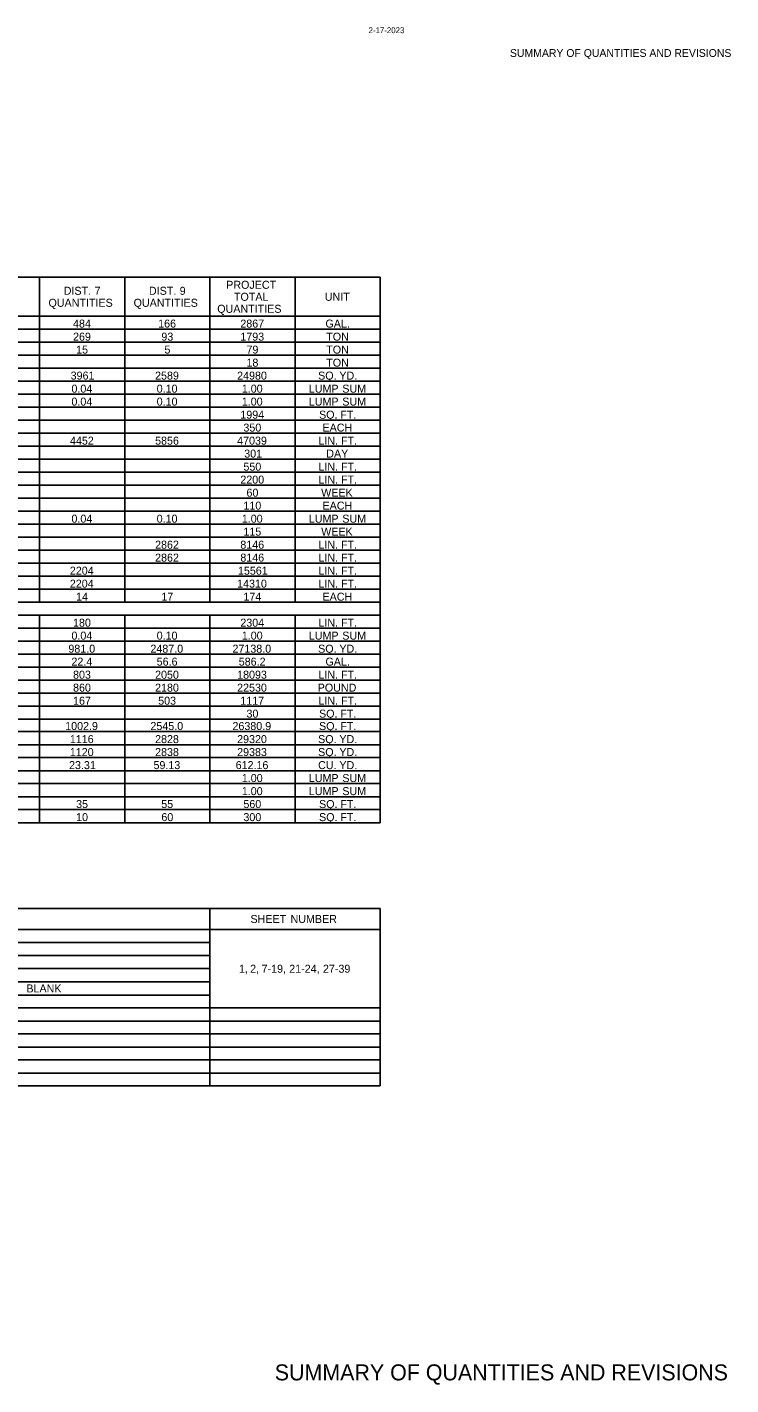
# Model space of a CAD drawing. Extents: x 544255 to 1930787, y -1947044 to 596640.
# Drawn here: x 556640 to 557167, y -1947044 to -1946026 of the extents above; entities that cross this region are included whole.
import ezdxf

# ---------------------------------------------------------------- set-up
doc = ezdxf.new("R2010")
doc.units = 0
for name, color, linetype in [('Default', 7, 'Continuous'), ('R_Border', 7, 'Continuous'), ('R_Border Prem', 7, 'Continuous')]:
    doc.layers.add(name, color=color, linetype=linetype)

msp = doc.modelspace()

# ---------------------------------------------------------------- linework, layer by layer
at = {"layer": 'Default'}
for p, q in [((555898, -1946213.6), (556904.2, -1946213.6)), ((556457.1, -1946213.6), (556904.2, -1946213.6)), ((556648.7, -1946457.4), (556648.7, -1946213.6)), ((556648.7, -1946242.9), (556648.7, -1946213.6)), ((556712.6, -1946457.4), (556712.6, -1946213.6)), ((556712.6, -1946242.9), (556712.6, -1946213.6)), ((556776.5, -1946457.4), (556776.5, -1946213.6)), ((556840.3, -1946457.4), (556840.3, -1946213.6)), ((556840.3, -1946457.4), (556840.3, -1946213.6)), ((556904.2, -1946622.7), (556904.2, -1946213.6)), ((555898, -1946242.9), (556904.2, -1946242.9)), ((555898, -1946242.9), (556904.2, -1946242.9)), ((555898, -1946252.6), (556904.2, -1946252.6)), ((555898, -1946262.4), (556904.2, -1946262.4)), ((555898, -1946272.1), (556904.2, -1946272.1)), ((555898, -1946281.9), (556904.2, -1946281.9)), ((555898, -1946291.6), (556904.2, -1946291.6)), ((555898, -1946301.4), (556904.2, -1946301.4)), ((555898, -1946311.1), (556904.2, -1946311.1)), ((555898, -1946320.9), (556904.2, -1946320.9)), ((555898, -1946330.6), (556904.2, -1946330.6)), ((555898, -1946340.4), (556904.2, -1946340.4)), ((555898, -1946350.1), (556904.2, -1946350.1)), ((555898, -1946359.9), (556904.2, -1946359.9)), ((555898, -1946369.6), (556904.2, -1946369.6)), ((555898, -1946379.4), (556904.2, -1946379.4)), ((555898, -1946389.1), (556904.2, -1946389.1)), ((555898, -1946398.9), (556904.2, -1946398.9)), ((555898, -1946408.6), (556904.2, -1946408.6)), ((555898, -1946418.4), (556904.2, -1946418.4)), ((555898, -1946428.1), (556904.2, -1946428.1)), ((555898, -1946437.9), (556904.2, -1946437.9)), ((555898, -1946447.6), (556904.2, -1946447.6)), ((555898, -1946457.4), (556904.2, -1946457.4)), ((555898, -1946457.4), (556904.2, -1946457.4)), ((555898, -1946467.1), (556904.2, -1946467.1)), ((555898, -1946467.1), (556904.2, -1946467.1)), ((556648.7, -1946622.7), (556648.7, -1946467.1)), ((556712.6, -1946622.7), (556712.6, -1946467.1)), ((556776.5, -1946622.7), (556776.5, -1946467.1)), ((556840.3, -1946622.7), (556840.3, -1946467.1)), ((555898, -1946476.9), (556904.2, -1946476.9)), ((555898, -1946486.6), (556904.2, -1946486.6)), ((555898, -1946496.4), (556904.2, -1946496.4)), ((555898, -1946506.1), (556904.2, -1946506.1)), ((555898, -1946515.9), (556904.2, -1946515.9)), ((555898, -1946525.6), (556904.2, -1946525.6)), ((555898, -1946535.4), (556904.2, -1946535.4)), ((555898, -1946545.1), (556904.2, -1946545.1)), ((555898, -1946554.4), (556904.2, -1946554.4)), ((555898, -1946564.2), (556904.2, -1946564.2)), ((555898, -1946573.9), (556904.2, -1946573.9)), ((555898, -1946583.7), (556904.2, -1946583.7)), ((555898, -1946593.4), (556904.2, -1946593.4)), ((555898, -1946603.2), (556904.2, -1946603.2)), ((555898, -1946612.9), (556904.2, -1946612.9)), ((555898, -1946622.7), (556904.2, -1946622.7)), ((555898, -1946687.1), (556904.2, -1946687.1)), ((556776.5, -1946702.7), (556776.5, -1946687.1)), ((556776.5, -1946820.1), (556776.5, -1946687.1)), ((556904.2, -1946820.1), (556904.2, -1946687.1)), ((555898, -1946702.7), (556904.2, -1946702.7)), ((555968.7, -1946712.4), (556776.5, -1946712.4)), ((555968.7, -1946722.2), (556776.5, -1946722.2)), ((555968.7, -1946731.9), (556776.5, -1946731.9)), ((555968.7, -1946742.1), (556776.5, -1946742.1)), ((555968.7, -1946751.9), (556776.5, -1946751.9)), ((555898, -1946761.6), (556904.2, -1946761.6)), ((556776.5, -1946761.6), (556904.2, -1946761.6)), ((555898, -1946771.4), (556904.2, -1946771.4)), ((555898, -1946781.1), (556904.2, -1946781.1)), ((555898, -1946790.9), (556904.2, -1946790.9)), ((555898, -1946800.6), (556904.2, -1946800.6)), ((555898, -1946810.4), (556904.2, -1946810.4)), ((555898, -1946820.1), (556904.2, -1946820.1))]:
    msp.add_line(p, q, dxfattribs=at)

# ---------------------------------------------------------------- texts
for s, p in [('PROJECT', (556788.7, -1946222.3)), ('DIST.', (556666.9, -1946226.8)), (' 7', (556687.8, -1946226.8)), ('DIST.', (556730.8, -1946226.8)), (' 9', (556751.6, -1946226.8)), ('TOTAL', (556794.5, -1946231.3)), ('UNIT', (556862.6, -1946231.3)), ('QUANTITIES', (556655.5, -1946235.8)), ('QUANTITIES', (556719.3, -1946235.8)), ('QUANTITIES', (556782, -1946240.3)), ('484', (556673.9, -1946251.4)), ('166', (556737.7, -1946251.4)), ('2867', (556799.3, -1946251.4)), ('GAL.', (556863.1, -1946251.4)), ('269', (556673.9, -1946261.2)), ('93', (556740.1, -1946261.2)), ('1793', (556799.3, -1946261.2)), ('TON', (556863.7, -1946261.2)), ('15', (556676.2, -1946270.9)), ('5', (556742.4, -1946270.9)), ('79', (556803.9, -1946270.9)), ('TON', (556863.7, -1946270.9)), ('18', (556803.9, -1946280.7)), ('TON', (556863.7, -1946280.7)), ('3961', (556672.1, -1946290.4)), ('2589', (556735.4, -1946290.4)), ('24980', (556796.9, -1946290.4)), ('SQ.', (556857.6, -1946290.4)), (' YD.', (556871.3, -1946290.4)), ('0.04', (556672.7, -1946300.2)), ('0.10', (556736.6, -1946300.2)), ('1.00', (556800.4, -1946300.2)), ('LUMP', (556850.6, -1946300.2)), (' SUM', (556873.5, -1946300.2)), ('0.04', (556672.7, -1946309.9)), ('0.10', (556736.6, -1946309.9)), ('1.00', (556800.4, -1946309.9)), ('LUMP', (556850.6, -1946309.9)), (' SUM', (556873.5, -1946309.9)), ('1994', (556799.3, -1946319.7)), ('SQ.', (556858.3, -1946319.7)), (' FT.', (556872, -1946319.7)), ('350', (556801.6, -1946329.4)), ('EACH', (556860.9, -1946329.4)), ('4452', (556671.6, -1946339.2)), ('5856', (556735.4, -1946339.2)), ('47039', (556796.9, -1946339.2)), ('LIN.', (556857.8, -1946339.2)), (' FT.', (556872.5, -1946339.2)), ('301', (556802.2, -1946348.9)), ('DAY', (556863.7, -1946348.9)), ('550', (556801.6, -1946358.7)), ('LIN.', (556857.8, -1946358.7)), (' FT.', (556872.5, -1946358.7)), ('2200', (556799.3, -1946368.4)), ('LIN.', (556857.8, -1946368.4)), (' FT.', (556872.5, -1946368.4)), ('60', (556803.9, -1946378.2)), ('WEEK', (556859.9, -1946378.2)), ('110', (556801.6, -1946387.9)), ('EACH', (556860.9, -1946387.9)), ('0.04', (556672.7, -1946397.7)), ('0.10', (556736.6, -1946397.7)), ('1.00', (556800.4, -1946397.7)), ('LUMP', (556850.6, -1946397.7)), (' SUM', (556873.5, -1946397.7)), ('115', (556801.6, -1946407.4)), ('WEEK', (556859.9, -1946407.4)), ('2862', (556735.4, -1946417.2)), ('8146', (556799.3, -1946417.2)), ('LIN.', (556857.8, -1946417.2)), (' FT.', (556872.5, -1946417.2)), ('2862', (556735.4, -1946426.9)), ('8146', (556799.3, -1946426.9)), ('LIN.', (556857.8, -1946426.9)), (' FT.', (556872.5, -1946426.9)), ('2204', (556671.5, -1946436.7)), ('2204', (556671.5, -1946446.4)), ('14310', (556796.9, -1946446.4)), ('15561', (556797.5, -1946436.7)), ('LIN.', (556857.8, -1946436.7)), ('LIN.', (556857.8, -1946446.4)), (' FT.', (556872.5, -1946436.7)), (' FT.', (556872.5, -1946446.4)), ('14', (556676.2, -1946456.2)), ('17', (556740.1, -1946456.2)), ('174', (556801.6, -1946456.2)), ('EACH', (556860.9, -1946456.2)), ('180', (556673.9, -1946475.7)), ('2304', (556799.3, -1946475.7)), ('LIN.', (556857.8, -1946475.7)), (' FT.', (556872.5, -1946475.7)), ('0.04', (556672.7, -1946485.4)), ('0.10', (556736.6, -1946485.4)), ('1.00', (556800.4, -1946485.4)), ('LUMP', (556850.6, -1946485.4)), (' SUM', (556873.5, -1946485.4)), ('981.0', (556670.4, -1946495.2)), ('2487.0', (556731.9, -1946495.2)), ('27138.0', (556793.4, -1946495.2)), ('SQ.', (556857.6, -1946495.2)), (' YD.', (556871.3, -1946495.2)), ('22.4', (556672.7, -1946504.9)), ('56.6', (556736.6, -1946504.9)), ('586.2', (556798.1, -1946504.9)), ('GAL.', (556863.1, -1946504.9)), ('803', (556673.9, -1946514.7)), ('2050', (556735.4, -1946514.7)), ('18093', (556796.9, -1946514.7)), ('LIN.', (556857.8, -1946514.7)), (' FT.', (556872.5, -1946514.7)), ('860', (556673.9, -1946524.4)), ('2180', (556735.4, -1946524.4)), ('22530', (556796.9, -1946524.4)), ('POUND', (556857.3, -1946524.4)), ('167', (556673.9, -1946534.2)), ('503', (556737.7, -1946534.2)), ('1117', (556799.3, -1946534.2)), ('LIN.', (556857.8, -1946534.2)), (' FT.', (556872.5, -1946534.2)), ('30', (556803.9, -1946543.9)), ('SQ.', (556858.3, -1946543.9)), (' FT.', (556872, -1946543.9)), ('1002.9', (556668, -1946553.2)), ('2545.0', (556731.9, -1946553.2)), ('26380.9', (556793.4, -1946553.2)), ('SQ.', (556858.3, -1946553.2)), (' FT.', (556872, -1946553.2)), ('1116', (556671.5, -1946563)), ('2828', (556735.4, -1946563)), ('29320', (556796.9, -1946563)), ('SQ.', (556857.6, -1946563)), (' YD.', (556871.3, -1946563)), ('1120', (556671.5, -1946572.7)), ('2838', (556735.4, -1946572.7)), ('29383', (556796.9, -1946572.7)), ('SQ.', (556857.6, -1946572.7)), (' YD.', (556871.3, -1946572.7)), ('23.31', (556670.9, -1946582.5)), ('59.13', (556734.2, -1946582.5)), ('612.16', (556795.8, -1946582.5)), ('CU.', (556857.6, -1946582.5)), (' YD.', (556871.3, -1946582.5)), ('1.00', (556800.4, -1946592.2)), ('LUMP', (556850.6, -1946592.2)), (' SUM', (556873.5, -1946592.2)), ('1.00', (556800.4, -1946602)), ('LUMP', (556850.6, -1946602)), (' SUM', (556873.5, -1946602)), ('35', (556676.2, -1946611.7)), ('55', (556740, -1946611.7)), ('560', (556801.6, -1946611.7)), ('SQ.', (556858.3, -1946611.7)), (' FT.', (556872, -1946611.7)), ('10', (556676.2, -1946621.5)), ('60', (556740.1, -1946621.5)), ('300', (556801.6, -1946621.5)), ('SQ.', (556858.3, -1946621.5)), (' FT.', (556872, -1946621.5)), ('SHEET', (556806.9, -1946697.9)), (' NUMBER', (556834.7, -1946697.9)), ('1,', (556798.2, -1946735.2)), (' 2,', (556804.4, -1946735.2)), (' 7-19,', (556813, -1946735.2)), (' 21-24,', (556833.7, -1946735.2)), (' 27-39', (556859, -1946735.2)), (' BLANK', (556636.7, -1946750))]:
    msp.add_text(s, height=6, dxfattribs=at).set_placement(p)
at = {"layer": 'R_Border'}
msp.add_text('SUMMARY OF QUANTITIES AND REVISIONS', height=12, rotation=360, dxfattribs=at).set_placement((556825.1, -1947040.9))
at = {"layer": 'R_Border Prem'}
msp.add_text('2-17-2023', height=4.4, dxfattribs=at).set_placement((556895.4, -1946030.6))
msp.add_text('SUMMARY OF QUANTITIES AND REVISIONS', height=5.862, rotation=360, dxfattribs=at).set_placement((557001.4, -1946048.4))

doc.saveas('drawing.dxf')
